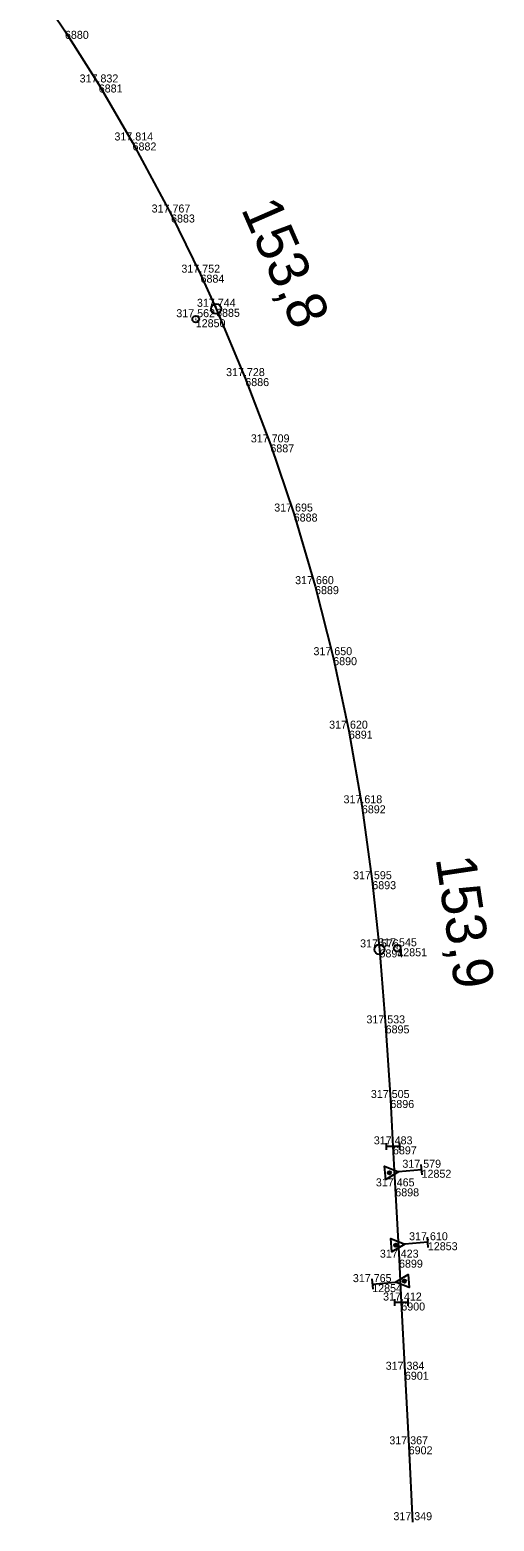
# Model space of a CAD drawing. Extents: x -544358 to -473583, y -1193502 to -1154121.
# Drawn here: x -500516.8 to -500447.2, y -1183562.2 to -1183338.6 of the extents above; entities that cross this region are included whole.
import ezdxf

# ---------------------------------------------------------------- set-up
doc = ezdxf.new("R2010")
doc.units = 0
for name, color, linetype in [('Vrstva 1', 7, 'Continuous'), ('Vrstva 3', 7, 'Continuous'), ('Vrstva 4', 7, 'Continuous'), ('Vrstva 60', 7, 'Continuous'), ('Vrstva 61', 7, 'Continuous'), ('Vrstva 7', 7, 'Continuous')]:
    doc.layers.add(name, color=color, linetype=linetype)

msp = doc.modelspace()

# ---------------------------------------------------------------- linework, layer by layer
at = {"layer": 'Vrstva 1'}
msp.add_lwpolyline([(-500516.77, -1183330.92), (-500511.51, -1183338.75), (-500506.44, -1183346.79), (-500501.37, -1183355.49), (-500495.6, -1183366.29), (-500491.18, -1183375.31), (-500488.85, -1183380.43), (-500484.47, -1183390.82), (-500480.71, -1183400.76), (-500477.21, -1183411.13), (-500474.01, -1183422.02), (-500471.29, -1183432.67), (-500468.94, -1183443.69), (-500466.99, -1183454.89), (-500465.43, -1183466.26), (-500464.35, -1183476.49), (-500463.43, -1183487.88), (-500462.72, -1183499.07), (-500462.33, -1183506.02), (-500461.98, -1183512.32), (-500461.42, -1183523.01), (-500461.08, -1183529.44), (-500460.54, -1183539.82), (-500459.97, -1183551), (-500459.38, -1183562.38)], dxfattribs=at)
at = {"layer": 'Vrstva 3'}
for p, q in [((-500463.33, -1183505.52), (-500463.33, -1183506.52)), ((-500461.33, -1183505.52), (-500461.33, -1183506.52)), ((-500461.33, -1183506.02), (-500463.33, -1183506.02)), ((-500462.08, -1183528.94), (-500462.08, -1183529.94)), ((-500460.08, -1183529.44), (-500462.08, -1183529.44)), ((-500460.08, -1183528.94), (-500460.08, -1183529.94))]:
    msp.add_line(p, q, dxfattribs=at)
at = {"layer": 'Vrstva 4'}
for p, q in [((-500462.67, -1183510.14), (-500463.04, -1183509.82)), ((-500457.97, -1183510.3), (-500458.1, -1183508.75)), ((-500461.98, -1183512.32), (-500461.42, -1183523.01)), ((-500461.74, -1183521), (-500462.11, -1183520.69)), ((-500457.04, -1183521.17), (-500457.17, -1183519.62)), ((-500465.5, -1183525.9), (-500465.37, -1183527.45)), ((-500460.8, -1183526.07), (-500460.43, -1183526.39))]:
    msp.add_line(p, q, dxfattribs=at)
for points in [[(-500458.04, -1183509.53), (-500461.5, -1183509.83), (-500463.42, -1183510.99), (-500463.59, -1183509), (-500461.5, -1183509.83)], [(-500457.1, -1183520.4), (-500460.57, -1183520.7), (-500462.48, -1183521.85), (-500462.66, -1183519.86), (-500460.57, -1183520.7)], [(-500465.44, -1183526.68), (-500461.97, -1183526.38), (-500460.06, -1183525.22), (-500459.88, -1183527.21), (-500461.97, -1183526.38)]]:
    msp.add_lwpolyline(points, dxfattribs=at)
for centre in [(-500462.86, -1183509.98), (-500461.92, -1183520.84), (-500460.62, -1183526.23)]:
    msp.add_circle(centre, 0.248, dxfattribs=at)
at = {"layer": 'Vrstva 60'}
for p, q in [((-500511.51, -1183338.75), (-500511.51, -1183338.75)), ((-500506.44, -1183346.79), (-500506.44, -1183346.79)), ((-500501.37, -1183355.49), (-500501.37, -1183355.49)), ((-500495.6, -1183366.29), (-500495.6, -1183366.29)), ((-500491.18, -1183375.31), (-500491.18, -1183375.31)), ((-500488.85, -1183380.43), (-500488.85, -1183380.43)), ((-500491.9, -1183381.99), (-500491.9, -1183381.99)), ((-500484.47, -1183390.82), (-500484.47, -1183390.82)), ((-500480.71, -1183400.76), (-500480.71, -1183400.76)), ((-500477.21, -1183411.13), (-500477.21, -1183411.13)), ((-500474.01, -1183422.02), (-500474.01, -1183422.02)), ((-500471.29, -1183432.67), (-500471.29, -1183432.67)), ((-500468.94, -1183443.69), (-500468.94, -1183443.69)), ((-500466.99, -1183454.89), (-500466.99, -1183454.89)), ((-500465.43, -1183466.26), (-500465.43, -1183466.26)), ((-500464.35, -1183476.49), (-500464.35, -1183476.49)), ((-500461.68, -1183476.32), (-500461.68, -1183476.32)), ((-500463.43, -1183487.88), (-500463.43, -1183487.88)), ((-500462.72, -1183499.07), (-500462.72, -1183499.07)), ((-500462.33, -1183506.02), (-500462.33, -1183506.02)), ((-500458.04, -1183509.53), (-500458.04, -1183509.53)), ((-500461.98, -1183512.32), (-500461.98, -1183512.32)), ((-500457.1, -1183520.4), (-500457.1, -1183520.4)), ((-500461.42, -1183523.01), (-500461.42, -1183523.01)), ((-500465.44, -1183526.68), (-500465.44, -1183526.68)), ((-500461.08, -1183529.44), (-500461.08, -1183529.44)), ((-500460.54, -1183539.82), (-500460.54, -1183539.82)), ((-500459.97, -1183551), (-500459.97, -1183551))]:
    msp.add_line(p, q, dxfattribs=at)
at = {"layer": 'Vrstva 7'}
for p, q in [((-500491.95, -1183381.99), (-500491.85, -1183381.99)), ((-500461.73, -1183476.32), (-500461.63, -1183476.32))]:
    msp.add_line(p, q, dxfattribs=at)
for centre, radius in [((-500488.85, -1183380.43), 0.75), ((-500491.9, -1183381.99), 0.5), ((-500464.35, -1183476.49), 0.75), ((-500461.68, -1183476.32), 0.5)]:
    msp.add_circle(centre, radius, dxfattribs=at)

# ---------------------------------------------------------------- texts
at = {"layer": 'Vrstva 60'}
for s, p in [('6880', (-500511.51, -1183339.95)), ('6881', (-500506.44, -1183347.99)), ('6882', (-500501.37, -1183356.69)), ('6883', (-500495.6, -1183367.49)), ('6884', (-500491.18, -1183376.51)), ('6885', (-500488.85, -1183381.63)), ('12850', (-500491.9, -1183383.19)), ('6886', (-500484.47, -1183392.02)), ('6887', (-500480.71, -1183401.96)), ('6888', (-500477.21, -1183412.33)), ('6889', (-500474.01, -1183423.22)), ('6890', (-500471.29, -1183433.87)), ('6891', (-500468.94, -1183444.89)), ('6892', (-500466.99, -1183456.08)), ('6893', (-500465.43, -1183467.46)), ('6894', (-500464.35, -1183477.69)), ('12851', (-500461.68, -1183477.52)), ('6895', (-500463.43, -1183489.08)), ('6896', (-500462.72, -1183500.27)), ('6897', (-500462.33, -1183507.22)), ('12852', (-500458.04, -1183510.73)), ('6898', (-500461.98, -1183513.52)), ('12853', (-500457.1, -1183521.6)), ('6899', (-500461.42, -1183524.21)), ('12854', (-500465.44, -1183527.88)), ('6900', (-500461.08, -1183530.64)), ('6901', (-500460.54, -1183541.02)), ('6902', (-500459.97, -1183552.2))]:
    msp.add_text(s, height=1.2, dxfattribs=at).set_placement(p)
at = {"layer": 'Vrstva 61'}
for s, p in [('317.832', (-500509.31, -1183346.49)), ('317.814', (-500504.09, -1183355.19)), ('317.767', (-500498.51, -1183365.99)), ('317.752', (-500494.05, -1183375.01)), ('317.562', (-500494.81, -1183381.69)), ('317.744', (-500491.72, -1183380.13)), ('317.728', (-500487.35, -1183390.52)), ('317.709', (-500483.64, -1183400.46)), ('317.695', (-500480.13, -1183410.83)), ('317.660', (-500477, -1183421.72)), ('317.650', (-500474.25, -1183432.37)), ('317.620', (-500471.9, -1183443.39)), ('317.618', (-500469.74, -1183454.58)), ('317.595', (-500468.31, -1183465.96)), ('317.576', (-500467.26, -1183476.19)), ('317.545', (-500464.55, -1183476.02)), ('317.533', (-500466.31, -1183487.58)), ('317.505', (-500465.64, -1183498.77)), ('317.483', (-500465.2, -1183505.72)), ('317.579', (-500460.92, -1183509.23)), ('317.465', (-500464.89, -1183512.02)), ('317.610', (-500459.91, -1183520.1)), ('317.423', (-500464.29, -1183522.71)), ('317.765', (-500468.34, -1183526.38)), ('317.412', (-500463.81, -1183529.14)), ('317.384', (-500463.42, -1183539.52)), ('317.367', (-500462.87, -1183550.7)), ('317.349', (-500462.26, -1183562.08))]:
    msp.add_text(s, height=1.2, dxfattribs=at).set_placement(p)
at = {"layer": 'Vrstva 7'}
for s, rotation, p in [('153,8', 293.6054, (-500485.16, -1183365.46)), ('153,9', 278.5153, (-500455.95, -1183462.83))]:
    msp.add_text(s, height=6, rotation=rotation, dxfattribs=at).set_placement(p)

doc.saveas('drawing.dxf')
